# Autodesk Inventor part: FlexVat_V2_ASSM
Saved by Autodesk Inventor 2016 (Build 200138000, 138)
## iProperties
Created: 2015-11
Part Number: FlexVat_V2_ASSM
Material: Generic
Document SubType Name: Modeling
Designer: John
Density: 1 g/cm^3
Appearance: Default
Author: John
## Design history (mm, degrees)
feature "Base1"
body "Solid1"
